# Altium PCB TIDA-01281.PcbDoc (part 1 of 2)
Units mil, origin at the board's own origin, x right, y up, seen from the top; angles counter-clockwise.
Board outline 2559.06 x 2165.35 mil, 4 copper layers (Top Layer, GND, SIGNAL, Bottom Layer), stack 60.234 mil thick; 109 components, 85 nets, 348 pads, 231 vias.
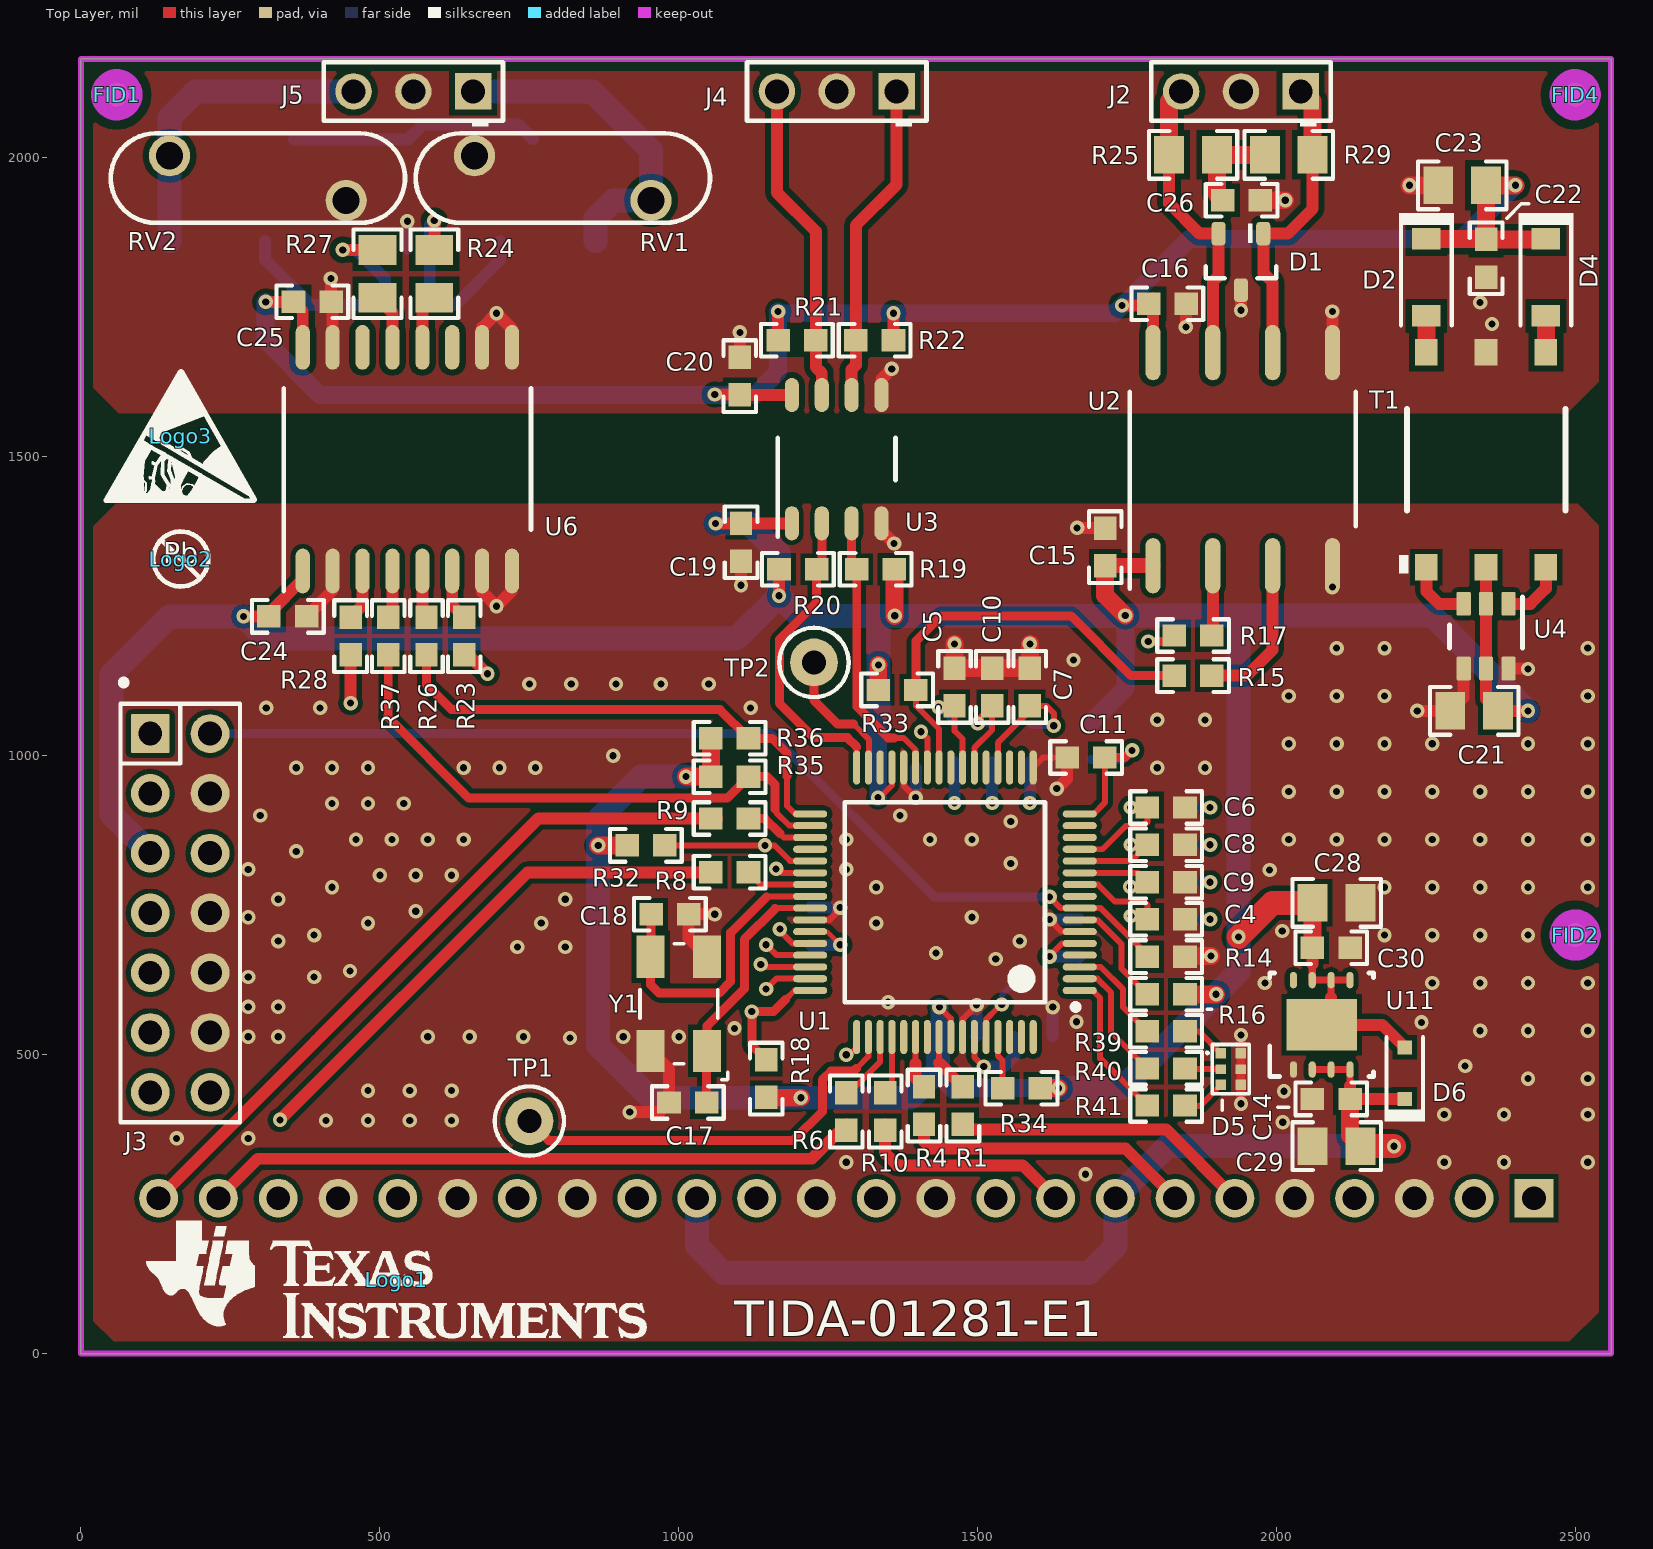
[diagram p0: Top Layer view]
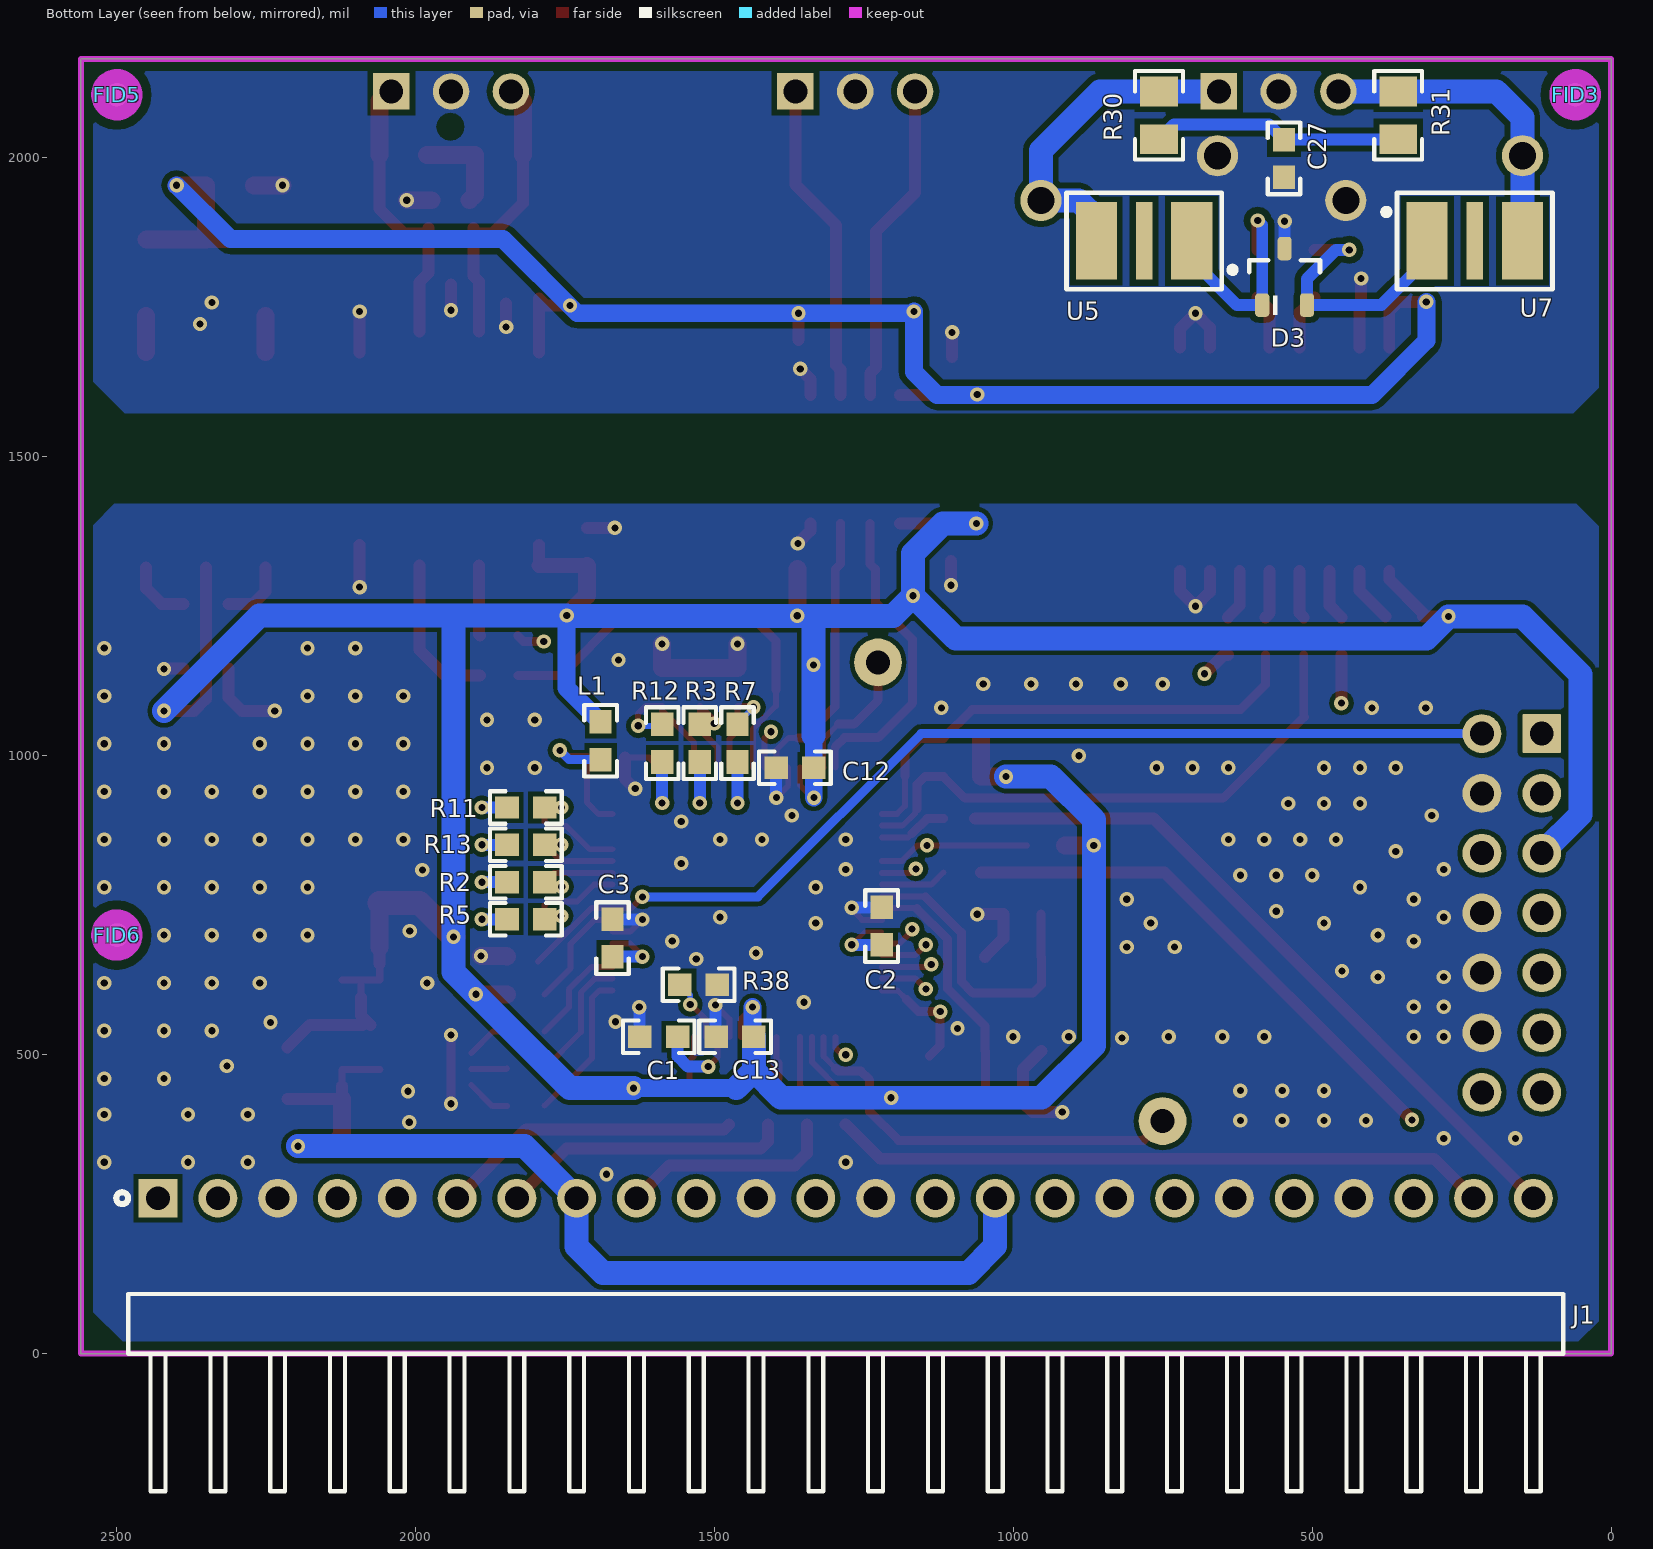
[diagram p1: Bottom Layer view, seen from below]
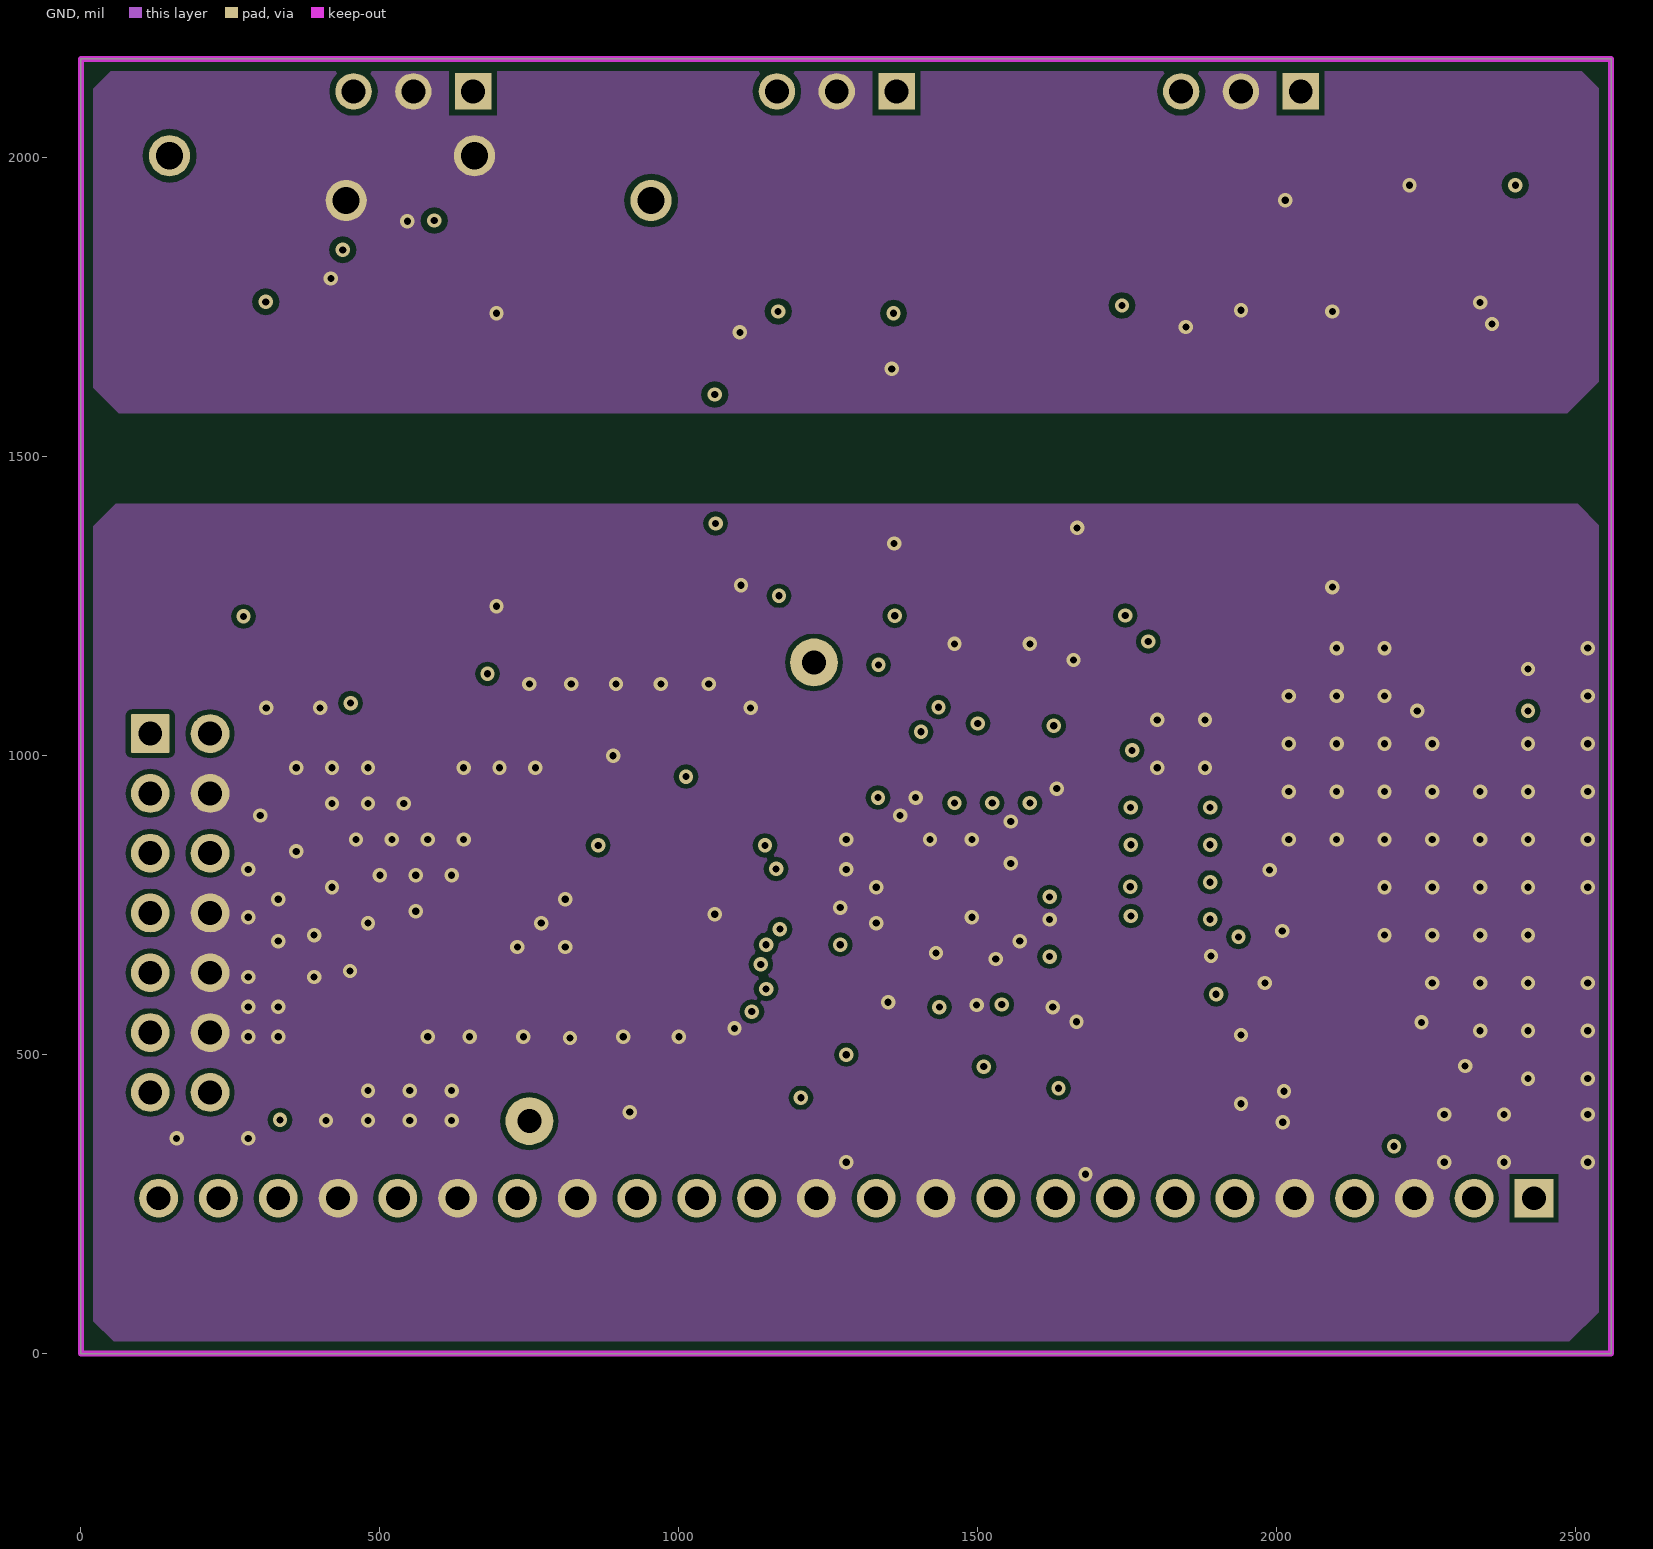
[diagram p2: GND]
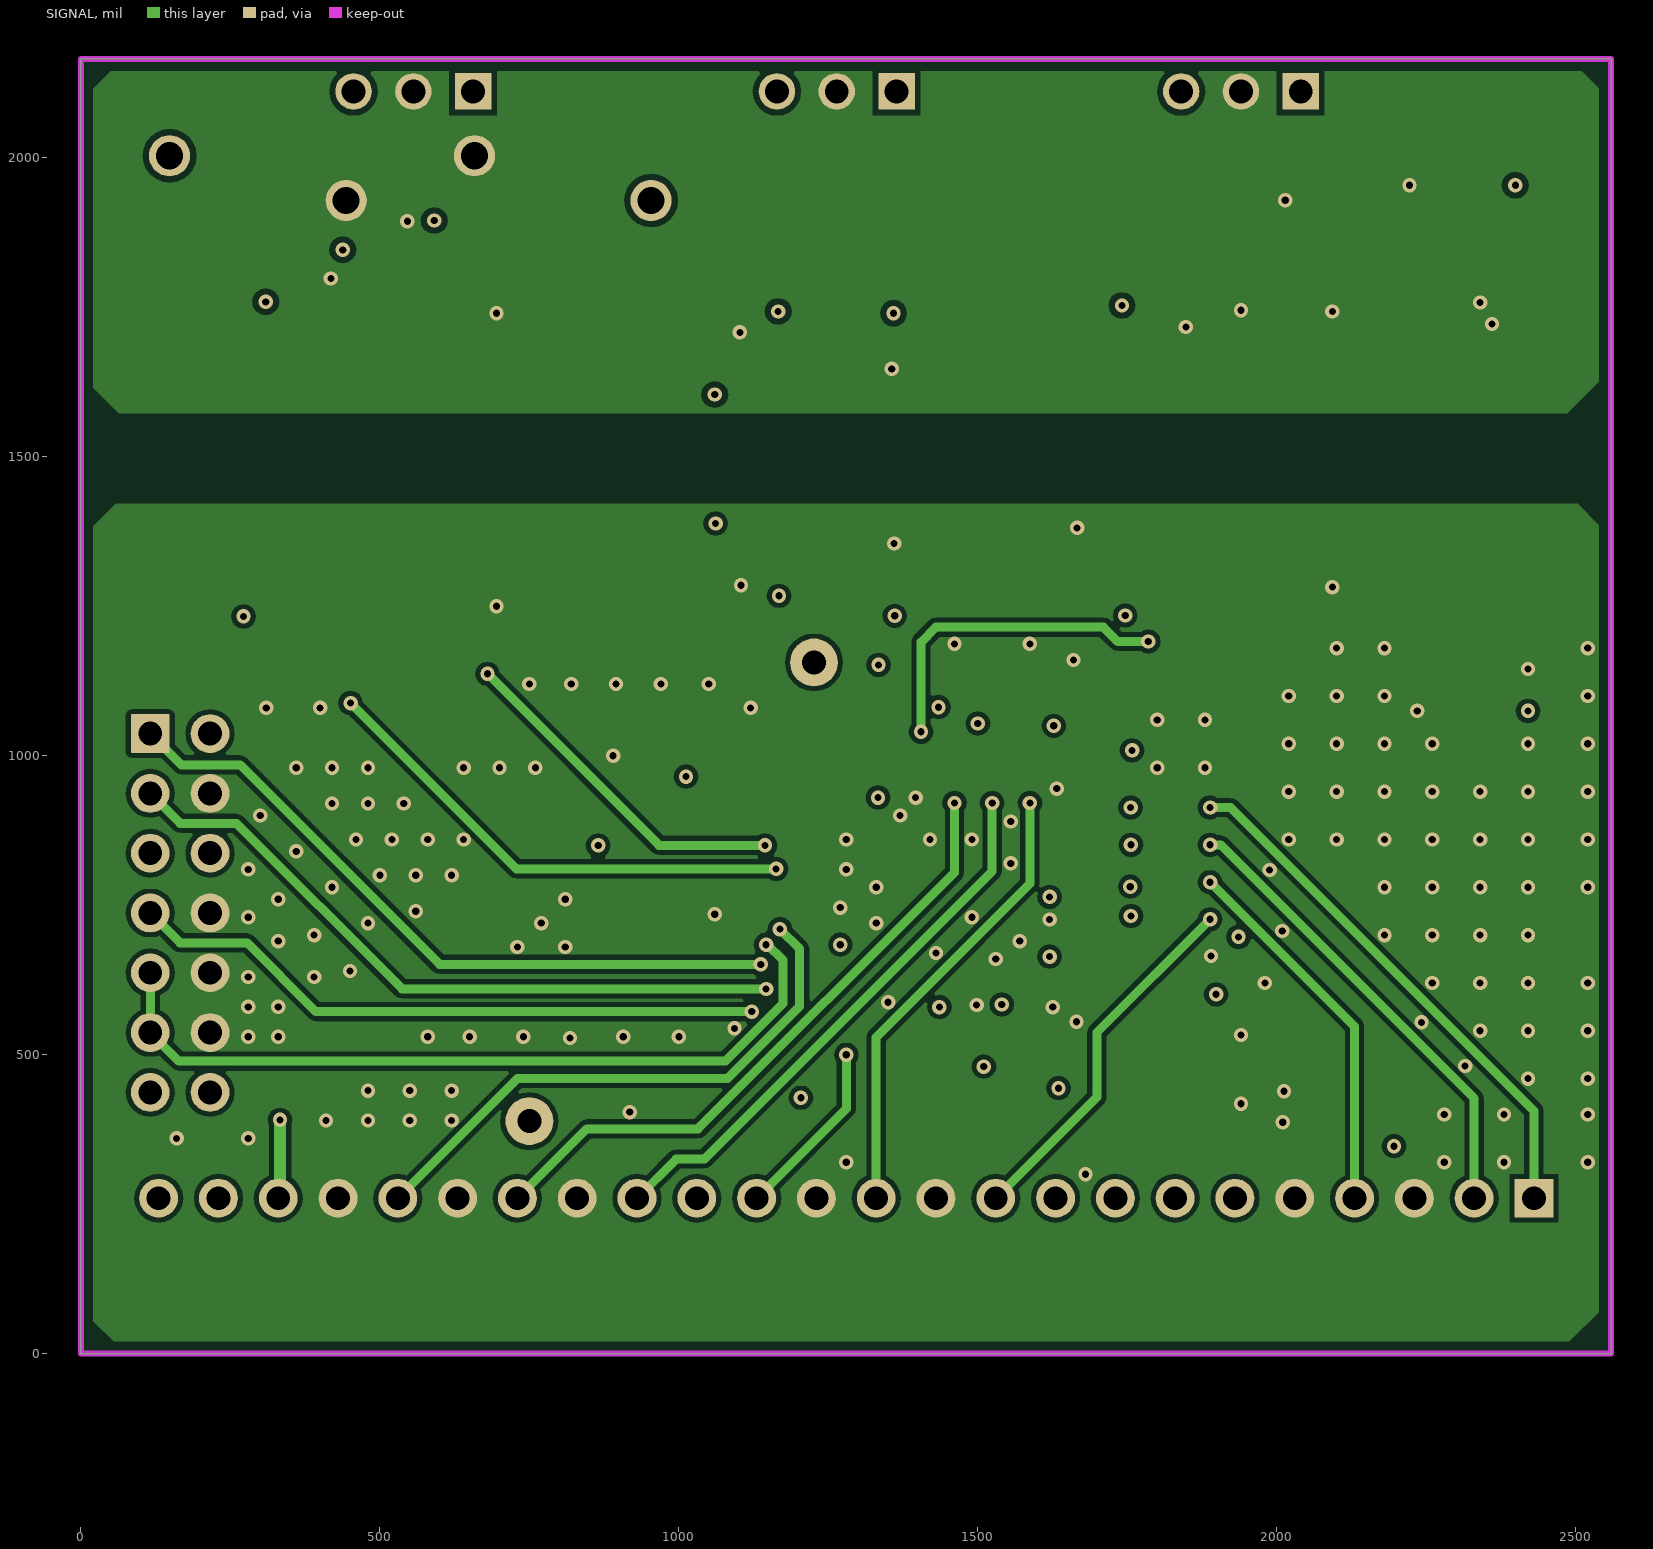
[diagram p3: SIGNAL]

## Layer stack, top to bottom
Top Solder: solder mask 0.4, Solder Resist, Dk 3.5
Top Layer: signal copper 0.7
Dielectric1: core 10, FR-4 High Tg, Dk 4.8
GND: signal copper 1.417
Dielectric 2: prepreg 36, FR-4 High Tg, Dk 4.2
SIGNAL: signal copper 1.417
Dielectric 3: core 10, FR-4 High Tg, Dk 4.2
Bottom Layer: signal copper 0.7
Bottom Solder: solder mask 0.4, Solder Resist, Dk 3.5

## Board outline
0,0 0,2165.36 2559.06,2165.36 2559.06,0

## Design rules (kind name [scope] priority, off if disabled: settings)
AcuteAngle [All] p1: minimum=4.50000000000000E+0001 checktracksonly=FALSE
AssemblyTestPointUsage [All] p1: valid=2
Clearance Clearance_Keepouts [((IsTrack Or IsArc) And Not InPoly) And IsFree and IsKeepOut vs ((IsTrack Or IsArc) And Not InPoly) And IsFree and IsKeepOut] p1: gap=20
Clearance Clearance_BoardEdge_MountingHoles [OnCopper and InComponentClass('Mounting Holes') vs IsKeepOut] p2: gap=40
Clearance Clearance_BoardEdge_Poly [OnCopper and InPoly vs IsKeepOut] p3: gap=15
Clearance Clearance_BoardEdge [OnCopper and Not InComponentClass('Logo') and not InComponentClass('FiducialMark') and not InRegion(1000,500,4000,800) and Not IsKeepout vs IsKeepOut] p4: gap=15
Clearance Clearance_Poly [InPolygon] p5: gap=8
Clearance [All] p6: gap=7.87
ComponentClearance ComponentClearance_MountingHoles_FiducialMarks [InComponentClass('Mounting Holes') vs InComponentClass('FiducialMark')] p1: gap=50 collisioncheckmode=3 verticalgap=10 showdistances=FALSE
ComponentClearance ComponentClearance_Shunt [InComponentClass('Header') vs InComponentClass('Shunt')] p2: gap=0 collisioncheckmode=3 verticalgap=0 showdistances=FALSE
ComponentClearance ComponentClearance_Logo [InComponentClass('Logo')] p3: gap=50 collisioncheckmode=3 verticalgap=10 showdistances=FALSE
ComponentClearance ComponentClearance_ScrewToNut [(HasFootprint('NY PMS 440 0025 PH')) vs (HasFootprint('Keystone_1902C'))] p4: gap=5 collisioncheckmode=3 verticalgap=10 showdistances=FALSE
ComponentClearance ComponentClearance_MountingHoles [InComponentClass('Mounting Holes')] p5: gap=200 collisioncheckmode=3 verticalgap=100000 showdistances=FALSE
ComponentClearance ComponentClearance_SmallPassives [HasFootprint('0201*') or HasFootprint('0402*') or HasFootprint('0508') or HasFootprint('0603*') or HasFootprint('0612') or HasFootprint('0805*') or HasFootprint('0815*') or HasFootprint('0830*') or HasFootprint('1206*') or HasFootprint('1210*') or HasFootprint('1808*') or HasFootprint('1812*') or HasFootprint('1825*') or HasFootprint('2010*') or HasFootprint('2220*') or HasFootprint('2225*') or HasFootprint('2512*') or HasFootprint('2728*') or HasFootprint('3518*') vs HasFootprint('0201*') or HasFootprint('0402*') or HasFootprint('0508') or HasFootprint('0603*') or HasFootprint('0612') or HasFootprint('0805*') or HasFootprint('0815*') or HasFootprint('0830*') or HasFootprint('1206*') or HasFootprint('1210*') or HasFootprint('1808*') or HasFootprint('1812*') or HasFootprint('1825*') or HasFootprint('2010*') or HasFootprint('2220*') or HasFootprint('2225*') or HasFootprint('2512*') or HasFootprint('2728*') or HasFootprint('3518*')] p6: gap=20 collisioncheckmode=3 verticalgap=10 showdistances=FALSE
ComponentClearance ComponentClearance_THtoSMT [IsThruComponent vs IsSMTComponent] p7: gap=20 collisioncheckmode=3 verticalgap=20 showdistances=FALSE
ComponentClearance ComponentClearance_THtoTH [IsThruComponent vs IsThruComponent] p8: gap=10 collisioncheckmode=3 verticalgap=10 showdistances=FALSE
ComponentClearance [All] p9: gap=20 collisioncheckmode=3 verticalgap=10 showdistances=FALSE
DiffPairsRouting [All] p1: maxlimit=100 minlimit=10 mostfreqgap=10 toplayer_minwidth=15 toplayer_maxwidth=15 toplayer_prefwidth=15 midlayer1_minwidth=15 midlayer1_maxwidth=15 midlayer1_prefwidth=15 midlayer2_minwidth=15 midlayer2_maxwidth=15 midlayer2_prefwidth=15 bottomlayer_minwidth=15 bottomlayer_maxwidth=15 bottomlayer_prefwidth=15 maxuncoupledlength=1000
FabricationTestPointUsage TestPointUsage [All] p1: valid=2 allowmultiple=FALSE
FabricationTestpoint Testpoint [All] p1: side=3 testpointundercomponent=TRUE minsize=40 maxsize=100 preferedsize=60 minholesize=0 maxholesize=40 preferedholesize=32 testpointgrid=1 allowsidetop=TRUE allowsidebottom=TRUE usegrid=TRUE gridtolerance=0.01
FanoutControl Fanout_LCC [IsLCC] p1: bgadir=Out bgaviamode=Centered fanoutstyle=Auto fanoutdirection=Alternating viagrid=1 // Fanout_LCC (Default Rule)
FanoutControl Fanout_BGA [IsBGA] p2: bgadir=Out bgaviamode=Centered fanoutstyle=Auto fanoutdirection=Alternating viagrid=1 // Fanout_BGA (Default Rule)
FanoutControl Fanout_Default [All] p4: bgadir=Out bgaviamode=Centered fanoutstyle=Auto fanoutdirection=Alternating viagrid=1 // Fanout_Default (Default Rule)
FanoutControl Fanout_Small [(CompPinCount < 5)] p5: bgadir=Out bgaviamode=Centered fanoutstyle=Auto fanoutdirection=OutThenIn viagrid=1 // Fanout_Small (Default Rule)
HoleSize [All] p1: absolutevalues=TRUE maxlimit=251 minlimit=8 maxpercent=80.000 minpercent=20.000
MinimumAnnularRing MinimumAnnularRing_ThermalPadVias [IsVia and InAnyComponent] p1: minimumring=5.91
MinimumAnnularRing [All] p2: minimumring=6
MinimumSolderMaskSliver MinimumSolderMaskSliver_Logo [InComponentClass('Logo') vs InComponentClass('Logo')] p1: minsoldermaskwidth=0.7
MinimumSolderMaskSliver [All] p2: minsoldermaskwidth=3.94
PlaneConnect [All] p1: planeconnectstyle=Relief reliefexpansion=10 reliefentries=4 reliefconductorwidth=10 reliefairgap=10
PolygonConnect [All] p1: connectstyle=Direct reliefconductorwidth=10 reliefentries=4 polygonreliefangle="90 Angle" airgapwidth=10
RoutingVias ThermalPadVias [IsVia and InAnyComponent] p1: holewidth=7.87 width=19.68 viastyle="Through Hole" minholewidth=7.87 minwidth=19.68 maxholewidth=12.99 maxwidth=23.62
RoutingVias [All] p2: holewidth=12 width=24 viastyle="Through Hole" minholewidth=12 minwidth=24 maxholewidth=40 maxwidth=65
SilkToBoardRegionClearance [Not ((IsComment or IsDesignator) And (Hide <> 'False')) and not InRegion(1000,500,4000,800)] p1:
SilkToSilkClearance SilkToSilkClearance_Pb-FreeLogo [(HasFootprint('Pb-Free_Overlay_Medium') OR HasFootprint('Pb-Free_Overlay_Small')) vs (HasFootprint('Pb-Free_Overlay_Medium') OR HasFootprint('Pb-Free_Overlay_Small'))] p1: silktosilkclearance=0
SilkToSilkClearance [All] p2: silktosilkclearance=4
SilkToSolderMaskClearance "Silk to Solder Mask Opening" [All] p1: minsilkscreentomaskgap=4 clearancetoexposedcopper=FALSE
SolderMaskExpansion [All] p1: expansion=1.97
UnpouredPolygon [All] p1: allowunpoured=FALSE
Width [All] p1: maxlimit=40 minlimit=8 preferedwidth=20 checkconnectedcopper=TRUE
14 further rules are at their usual default settings.

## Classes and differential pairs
component class TIDA-01281_Sheet1: C1 C2 C3 C4 C5 C6 C7 C8 C9 C10 C11 C12 C13 C14 C15 C16 C17 C18 C19 C20 C21 C22 C23 C24 C25 C26 C27 C28 C29 C30 D1 D2 D3 D4 D5 D6 J1 J2 J3 J4 J5 L1 R1 R2 R3 R4 R5 R6 R7 R8 R9 R10 R11 R12 R13 R14 R15 R16 R17 R18 R19 R20 R21 R22 R23 R24 R25 R26 R27 R28 R29 R30 R31 R32 R33 R34 R35 R36 R37 R38 R39 R40 R41 RV1 RV2 T1 TP1 TP2 U1 U2 U3 U4 U5 U6 U7 U11 Y1
component class AssemblyNote: ZZ1 ZZ2 ZZ3
component class FiducialMark: FID1 FID2 FID3 FID4 FID5 FID6
component class TIDA-01281_Hardware: FID1 FID2 FID3 FID4 FID5 FID6 Logo1 Logo2 Logo3 ZZ1 ZZ2 ZZ3
component class Logo: Logo1
component class Header: J1 J3

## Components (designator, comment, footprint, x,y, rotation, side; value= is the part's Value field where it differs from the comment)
C1 "C0603C125K9PACTU" 0603 1592.64,530 r0 bottom
C2 "C0603C125K9PACTU" 0603 1220,715 r90 bottom
C3 "C0603C125K9PACTU" 0603 1670,695 r270 bottom
C4 "06031C103JAT2A" 0603 1815,726.46 r0 top
C5 "06031C103JAT2A" 0603 1461,1115 r90 top
C6 "06031C103JAT2A" 0603 1815,913.46 r0 top
C7 "06031C103JAT2A" 0603 1587,1115 r90 top
C8 "UMK107AB7105KA-T" 0603 1815,851 r0 top
C9 "06031C102KAT2A" 0603 1815,788.46 r0 top
C10 "06031C102KAT2A" 0603 1524,1115 r90 top
C11 "C0603C125K9PACTU" 0603 1681,997 r180 top
C12 "C0603C125K9PACTU" 0603 1365,980 r0 bottom
C13 "C0603C125K9PACTU" 0603 1465,530 r0 bottom
C14 "06035A101JAT2A" 0603 2091,426 r0 top
C15 "06033C104JAT2A" 0603 1713,1349 r90 top
C16 "06033C104JAT2A" 0603 1817,1756 r0 top
C17 "GRM1885C2A150JA01D" 0603 1015,420 r180 top
C18 "GRM1885C2A150JA01D" 0603 985,735 r0 top
C19 "06033C104JAT2A" 0603 1104,1357 r270 top
C20 "06033C104JAT2A" 0603 1102,1635 r90 top
C21 "GRM21BZ71E106KE15L" 0805_HV 2330,1075 r0 top
C22 "8.850122061e+011" 0603 2350,1832 r90 top
C23 "GRM21BZ71E106KE15L" 0805_HV 2310,1954 r0 top
C24 "06033C104JAT2A" 0603 346,1233 r0 top
C25 "06033C104JAT2A" 0603 387,1759 r0 top
C26 "06031C472JAT2A" 0603 1941,1929 r180 top
C27 "06031C472JAT2A" 0603 547,1999 r90 bottom
C28 "06035A101JAT2A" 0603 2091,679 r180 top
C29 "GRM21BR61E106MA73" 0805_HV 2100,347 r0 top
C30 "GRM21BR61E106MA73" 0805_HV 2100,754 r180 top
D1 "CDSOT23-SM712" SOT-23 1940,1826 r270 top
D2 "1N5819HW-7-F" SOD-123 2250,1800 r270 top
D3 "CDSOT23-SM712" SOT-23 546,1801 r90 bottom
D4 "1N5819HW-7-F" SOD-123 2450,1800 r270 top
D5 "SMLP36RGB2W3" PicoLED_RGB_150x100 1923,476 r0 top
D6 "CMDSH2-3 TR" SOD-323 2214,469 r90 top
FID1 "Fiducial" Fiducial10-20#1 60,2105.36 r90 top
FID2 "Fiducial" Fiducial10-20#1 2499.06,700 r90 top
FID3 "Fiducial" Fiducial10-20#2 65,2100.36 r90 bottom
FID4 "Fiducial" Fiducial10-20#1 2499.06,2105.36 r90 top
FID5 "Fiducial" Fiducial10-20#1 2499.06,2105.36 r90 bottom
FID6 "Fiducial" Fiducial10-20#1 2499.06,700 r90 bottom
J1 "TSW-128-09-G-S-RE" CONN_TSW-128-09-X-S-RE 1080,260 r180 bottom
J2 "HTSW-103-09-G-S" Samtec_HTSW-103-09-x-S 1940,2111 r180 top
J3 "TSW-107-07-G-D" TSW-107-07-G-D 166,737 r270 top
J4 "HTSW-103-09-G-S" Samtec_HTSW-103-09-x-S 1264,2111 r180 top
J5 "HTSW-103-09-G-S" Samtec_HTSW-103-09-x-S 556,2111 r180 top
L1 "BLM18SG121TN1D" 0603 1690,1025 r270 bottom
Logo1 "Texas Instruments" TI_Stacked_Overlay_Small 528,124 r0 top
Logo2 "Pb-Free Symbol" Pb-Free_Overlay_Small 167,1329 r0 top
Logo3 "ESD Susceptible" ESD_Overlay_Medium 167,1534 r0 top
R1 "RC0603JR-070RL" 0603 1475,415 r270 top
R2 "CRCW06031K00JNEA" 0603 1815,788.46 r180 bottom
R3 "CRCW06031K00JNEA" 0603 1524,1021 r90 bottom
R4 "RC0603JR-070RL" 0603 1410,415 r270 top
R5 "CRCW06031K00JNEA" 0603 1815,726.46 r180 bottom
R6 "RC0603JR-070RL" 0603 1280,405 r270 top
R7 "CRCW06031K00JNEA" 0603 1461,1021 r90 bottom
R8 "RC0603JR-070RL" 0603 1085,805 r180 top
R9 "RC0603JR-070RL" 0603 1085,895 r180 top
R10 "RC0603JR-070RL" 0603 1345,405 r270 top
R11 "CRCW06031K00JNEA" 0603 1815,913.46 r180 bottom
R12 "CRCW06031K00JNEA" 0603 1587,1021 r90 bottom
R13 "CRCW06031K00JNEA" 0603 1815,851 r180 bottom
R14 "RC0603FR-074K7L" 0603 1815,664 r0 top
R15 "CRCW0603100RFKEA" 0603 1860,1134 r0 top
R16 "RC0603FR-074K7L" 0603 1815,601 r0 top
R17 "CRCW0603100RFKEA" 0603 1860,1201 r0 top
R18 "RC0603FR-0710KL" 0603 1146,460 r270 top
R19 "RC0603FR-074K7L" 0603 1329,1312 r180 top
R20 "RC0603FR-074K7L" 0603 1199,1312 r0 top
R21 "RC0603FR-074K7L" 0603 1197.5,1695 r0 top
R22 "RC0603FR-074K7L" 0603 1327.5,1695 r180 top
R23 "CRCW0603100RFKEA" 0603 641,1200 r270 top
R24 "CRT0805-BY-10R0ELF" 0805_HV 591,1806 r90 top
R25 "CRCW080560R4FKEA" 0805_HV 1860,2005 r0 top
R26 "CRCW0603100RFKEA" 0603 578,1200 r270 top
R27 "CRT0805-BY-10R0ELF" 0805_HV 496,1806 r90 top
R28 "CRCW0603100RFKEA" 0603 451,1200 r270 top
R29 "CRCW080560R4FKEA" 0805_HV 2020,2005 r0 top
R30 "CRCW080560R4FKEA" 0805_HV 756,2071 r270 bottom
R31 "CRCW080560R4FKEA" 0805_HV 356,2071 r90 bottom
R32 "CRCW06034K70JNEA" 0603 945,850 r0 top
R33 "CRCW06034K70JNEA" 0603 1365,1110 r0 top
R34 "RC0603FR-0710KL" 0603 1573,444 r0 top
R35 "CRCW06034K70JNEA" 0603 1085,965 r0 top
R36 "CRCW06034K70JNEA" 0603 1085,1029 r0 top
R37 "CRCW0603100RFKEA" 0603 514,1200 r270 top
R38 "RC0603FR-0710KL" 0603 1526,617 r180 bottom
R39 "CRCW06031K00JNEA" 0603 1815,539 r0 top
R40 "CRCW06031K00JNEA" 0603 1815,477 r0 top
R41 "CRCW06031K00JNEA" 0603 1815,415 r0 top
RV1 "MOV-10D201K" Bourns_MOV-10DxxxK 806,1966 r0 top
RV2 "MOV-10D201K" Bourns_MOV-10DxxxK 296,1966 r0 top
T1 "760390013" Wurth_760390013 2350,1495 r90 top
TP1 "5117" Keystone5117 750,389 r0 top
TP2 "5117" Keystone5117 1226,1156 r0 top
U1 "TMS320F28035PAGTR" PAG0064A_N 1445,755 r180 top
U2 "ISO1050DUB" DUB0008A_N 1943,1496 r90 top
U3 "ISO1541DR" D0008A_N 1264,1496 r90 top
U4 "SN6505BDBVR" DBV0006A_N 2350,1200 r270 top
U5 "TBU-CA065-200-WH" TBU-CA 781,1861 r0 bottom
U6 "ISO3082DW" DW0016A_N 546,1496 r90 top
U7 "TBU-CA065-200-WH" TBU-CA 228,1861 r180 bottom
U11 "TLV1117-50CDRJR" DRJ0008A 2075,550 r90 top
Y1 "ABM3B-20.000MHZ-10-1-U-T" ABRACON_ABM3B 1000,585 r180 top
ZZ1 "These assemblies are ESD sensitive, ESD precautions shall be observed." AssemblyNote -126,2792.6 r0 top
ZZ2 "These assemblies must be clean and free from flux and all contaminants. Use of no clean flux is not acceptable." AssemblyNote -126,2704.05 r0 top
ZZ3 "These assemblies must comply with workmanship standards IPC-A-610 Class 2, unless otherwise specified." AssemblyNote -126,2615.49 r0 top

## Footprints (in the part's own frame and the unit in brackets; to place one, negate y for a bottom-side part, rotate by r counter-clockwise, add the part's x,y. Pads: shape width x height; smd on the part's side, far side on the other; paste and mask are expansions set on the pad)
0603 [mm] "0603 from SM-752 data"
  rect 1x0.95 smd: 1(-0.8,0) 2(0.8,0)
  silkscreen extent -1.52,-0.69 1.52,0.69, body extent -0.87,-0.47 0.87,0.47, height 1
0805_HV [mil] "0805 with 30mil clearance between pads"
  rect 50x63 smd: 1(-40,0) 2(40,0)
  silkscreen extent -74,-40 74,40, body extent -43,-29 43,29, height 57
ABRACON_ABM3B [mm] "ABRACON"
  rect 1.2x1.8 smd: 1(-1.2,2) 2(-1.2,-2) 3(1.2,-2) 4(1.2,2)
  silkscreen extent -2.08,-2.55 1.65,3.22, body extent -1.65,-2.55 1.65,2.55, height 1.12
AssemblyNote [mil] "Assembly Note"
Bourns_MOV-10DxxxK [mm] "Bourns"
  round 1.75 hole 1.15: 1(-3.75,0.95) 2(3.75,-0.95)
  silkscreen extent -6.25,-1.9 6.25,1.9, body extent -6.23,-1.9 6.23,1.9, height 15.49
CONN_TSW-128-09-X-S-RE [mm] "Samtec 100mil, 1x28, Extended Right-angle"
  rect 1.65x1.65 hole 1.016 mask+0.064: 1(-34.29,0)
  round 1.65 hole 1.016 mask+0.064: 2(-31.75,0) 3(-29.21,0) 4(-26.67,0) 5(-24.13,0) 6(-21.59,0) 7(-19.05,0) 8(-16.51,0) 9(-13.97,0) 10(-11.43,0) 11(-8.89,0) 12(-6.35,0) 13(-3.81,0) 14(-1.27,0) 15(1.27,0) 16(3.81,0) 17(6.35,0) 18(8.89,0) 19(11.43,0) 20(13.97,0) 21(16.51,0) 22(19.05,0) 23(21.59,0) 24(24.13,0)
  silkscreen extent -35.56,-12.45 25.4,-4.06
D0008A_N [mm] "SOIC, 8-Leads, Body 4.9x3.9mm, Pitch 1.27mm, IPC Medium Density"
  oval 1.45x0.6 smd: 1(-2.725,1.905) 2(-2.725,0.635) 3(-2.725,-0.635) 4(-2.725,-1.905) 5(2.725,-1.905) 6(2.725,-0.635) 7(2.725,0.635) 8(2.725,1.905)
  silkscreen extent -3.3,-2.5 0.9,2.5, body extent -3,-2.45 3,2.45, height 1.63
DBV0006A_N [mm] "SOT23, 6-Leads, Body 2.9x1.6mm, Pitch 0.95mm, Lead Span 2.8mm, IPC Medium Density"
  rrect17% 1x0.6 smd: 1(-1.375,0.95) 2(-1.375,0) 3(-1.375,-0.95) 4(1.375,-0.95) 5(1.375,0) 6(1.375,0.95)
  silkscreen extent -1.68,-1.55 0.5,1.55, body extent -1.42,-1.46 1.42,1.46, height 1.12
DRJ0008A [mm] "SON, 8-Leads, Body 4x4mm, Pitch 0.8mm, Thermal Pad 3x2.2mm, TI Recommended"
  oval 0.7x0.3 smd: 1(-1.9,1.2) 2(-1.9,0.4) 3(-1.9,-0.4) 4(-1.9,-1.2) 5(1.9,-1.2) 6(1.9,-0.4) 7(1.9,0.4) 8(1.9,1.2)
  rect 2.2x3 smd paste-1.1: 9(0,0)
  silkscreen extent -2.2,-2.2 2.2,2.2, body extent -2.05,-2.05 2.05,2.05, height 0.81
DUB0008A_N [mm] "SOP, 8-Leads, Body 9.5x6.62mm, Pitch 2.54mm, IPC Medium Density"
  oval 2.35x0.65 smd: 1(-4.525,3.81) 2(-4.525,1.27) 3(-4.525,-1.27) 4(-4.525,-3.81) 5(4.525,-3.81) 6(4.525,-1.27) 7(4.525,1.27) 8(4.525,3.81)
  silkscreen extent -5.5,-4.8 2.85,4.8, body extent -5.21,-4.75 5.21,4.75, height 4.85
DW0016A_N [mm] "SOIC, 16-Leads, Body 10.3x7.5mm, Pitch 1.27mm, IPC Medium Density"
  oval 1.9x0.6 smd: 1(-4.75,4.445) 2(-4.75,3.175) 3(-4.75,1.905) 4(-4.75,0.635) 5(-4.75,-0.635) 6(-4.75,-1.905) 7(-4.75,-3.175) 8(-4.75,-4.445) 9(4.75,-4.445) 10(4.75,-3.175) 11(4.75,-1.905) 12(4.75,-0.635) 13(4.75,0.635) 14(4.75,1.905) 15(4.75,3.175) 16(4.75,4.445)
  silkscreen extent -5.6,-5.25 3,5.25, body extent -5.14,-5.13 5.14,5.13, height 2.54
ESD_Overlay_Medium [mil]
  silkscreen extent -127,-109 125,110
Fiducial10-20#1 [mm]
  round 1 smd mask+0.5: 1(0,0)
  Top Layer keep-out circle w1.178: c0,0 r0.5
Fiducial10-20#2 [mm]
  round 1 smd mask+0.5: 1(0.127,-0.127)
  Top Layer keep-out circle w1.178: c0.127,-0.127 r0.5
Keystone5117 [mil] "For Keystone 500x miniature loop terminals"
  round 80 hole 40: 1(0,0)
  silkscreen extent -58,-58 58,58, body extent -49,-49 49,49, height 182
PAG0064A_N [mm] "Thin QFP, 64-Leads, Body 10x10mm, Pitch 0.5mm, IPC Medium Density"
  oval 1.45x0.3 smd: 1(-5.725,3.75) 2(-5.725,3.25) 3(-5.725,2.75) 4(-5.725,2.25) 5(-5.725,1.75) 6(-5.725,1.25) 7(-5.725,0.75) 8(-5.725,0.25) 9(-5.725,-0.25) 10(-5.725,-0.75) 11(-5.725,-1.25) 12(-5.725,-1.75) 13(-5.725,-2.25) 14(-5.725,-2.75) 15(-5.725,-3.25) 16(-5.725,-3.75) 33(5.725,-3.75) 34(5.725,-3.25) 35(5.725,-2.75) 36(5.725,-2.25) 37(5.725,-1.75) 38(5.725,-1.25) 39(5.725,-0.75) 40(5.725,-0.25) 41(5.725,0.25) 42(5.725,0.75) 43(5.725,1.25) 44(5.725,1.75) 45(5.725,2.25) 46(5.725,2.75) 47(5.725,3.25) 48(5.725,3.75)
  oval 0.3x1.45 smd: 17(-3.75,-5.725) 18(-3.25,-5.725) 19(-2.75,-5.725) 20(-2.25,-5.725) 21(-1.75,-5.725) 22(-1.25,-5.725) 23(-0.75,-5.725) 24(-0.25,-5.725) 25(0.25,-5.725) 26(0.75,-5.725) 27(1.25,-5.725) 28(1.75,-5.725) 29(2.25,-5.725) 30(2.75,-5.725) 31(3.25,-5.725) 32(3.75,-5.725) 49(3.75,5.725) 50(3.25,5.725) 51(2.75,5.725) 52(2.25,5.725) 53(1.75,5.725) 54(1.25,5.725) 55(0.75,5.725) 56(0.25,5.725) 57(-0.25,5.725) 58(-0.75,5.725) 59(-1.25,5.725) 60(-1.75,5.725) 61(-2.25,5.725) 62(-2.75,5.725) 63(-3.25,5.725) 64(-3.75,5.725)
  silkscreen extent -5.68,-4.25 4.25,4.57, body extent -6,-6 6,6, height 1.09
Pb-Free_Overlay_Small [mil]
  silkscreen extent -46,-46 46,46
PicoLED_RGB_150x100 [mm] "SMD, 6-Leads, Body 1.5x1mm"
  rect 0.45x0.45 smd: 1(-0.425,0.675) 3(-0.425,-0.675) 4(0.425,-0.675) 6(0.425,0.675)
  rect 0.45x0.4 smd: 2(-0.425,0) 5(0.425,0)
  silkscreen extent -1.04,0.64 -0.94,0.74, body extent -0.5,-0.75 0.5,0.75, height 0.25
Samtec_HTSW-103-09-x-S [mm] "Header, 3x1, 2.54mm, TH"
  rect 1.55x1.55 hole 1.016: 1(-2.54,0)
  round 1.55 hole 1.016: 2(0,0) 3(2.54,0)
  silkscreen extent -3.81,-1.24 3.81,1.5, body extent -3.81,-1.24 3.81,1.24, height 8.38
SOD-123 [mm] "On Semi recommended land pattern"
  rect 0.915x1.22 smd: 1(-1.637,0) 2(1.637,0)
  silkscreen extent -2.74,-1.17 2.03,1.17, body extent -1.93,-0.9 1.93,0.9, height 1.35
SOD-323 [mm] "NXP recommended land pattern"
  rect 0.6x0.6 smd paste-0.05: 1(-1.1,0) 2(1.1,0)
  silkscreen extent -2.06,-0.86 1.53,0.86, body extent -1.3,-0.67 1.3,0.68, height 1.1
SOT-23 [mm] "SOT23, 3-Leads, Body 2.9x1.3mm, Pitch 0.95mm, Lead Span 2.5mm, IPC Medium Density"
  rrect50% 1x0.6 smd: 1(-1.2,0.95) 2(-1.2,-0.95) 3(1.2,0)
  silkscreen extent -1.63,-1.5 0.7,1.5, body extent -1.16,-1.45 1.21,1.45, height 1
TBU-CA [mm] "Bourns"
  rect 1.75x3.3 smd paste-0.012 mask+0.05: 1(-2.025,0) 3(2.025,0)
  rect 0.7x3.3 smd paste-0.012 mask+0.05: 2(0,0)
  silkscreen extent -3.89,-2.05 3.3,2.05, body extent -3.25,-2 3.25,2, height 0.87
TI_Stacked_Overlay_Small [mil]
  silkscreen extent -418,-98 418,98
TSW-107-07-G-D [mm] "Samtec 100mil, 2x7, 230 mil above insulator"
  rrect6% 1.65x1.65 hole 1.016: 1(-7.62,-1.27)
  round 1.65 hole 1.016: 2(-7.62,1.27) 3(-5.08,-1.27) 4(-5.08,1.27) 5(-2.54,-1.27) 6(-2.54,1.27) 7(0,-1.27) 8(0,1.27) 9(2.54,-1.27) 10(2.54,1.27) 11(5.08,-1.27) 12(5.08,1.27) 13(7.62,-1.27) 14(7.62,1.27)
  silkscreen extent -9.91,-2.54 8.89,2.54, body extent -8.89,-2.54 8.89,2.54, height 8.38
Wurth_760390013 [mil] "Wurth"
  rect 44x38 smd: 1(-180,100) 2(-180,0) 3(-180,-100) 4(180,-100) 5(180,0) 6(180,100)
  silkscreen extent -190,-132 85,145, body extent -198,-135 198,130, height 166

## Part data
C1 C2 C3 C11 C12 C13: "CAP, CERM, 1.2 µF, 6.3 V, +/- 10%, X5R, 0603"
C4 C5 C6 C7: "CAP, CERM, 0.01 µF, 100 V, +/- 5%, X7R, 0603"
C8: "CAP, CERM, 1 µF, 50 V, +/- 10%, X7R, 0603"
C9 C10: "CAP, CERM, 1000 pF, 100 V, +/- 10%, X7R, 0603"
C14 C28: "CAP, CERM, 100 pF, 50 V, +/- 5%, C0G/NP0, 0603"
C15 C16 C19 C20 C24 C25: "CAP, CERM, 0.1 µF, 25 V, +/- 5%, X7R, 0603"
C17 C18: "CAP, CERM, 15 pF, 100 V, +/- 5%, C0G/NP0, 0603"
C21 C23: "CAP, CERM, 10 µF, 25 V, +/- 10%, X7R, 0805"
C22: "CAP, CERM, 0.1 µF, 50 V, +/- 10%, X7R, 0603"
C26 C27: "CAP, CERM, 4700 pF, 100 V, +/- 5%, X7R, 0603"
C29 C30: "CAP, CERM, 10 µF, 25 V, +/- 20%, X5R, 0805"
D1 D3: "Diode, TVS, Bi, 7 V, 400 W, SOT-23"
D2 D4: "Diode, Schottky, 40 V, 1 A, SOD-123"
D5: "LED, Rgb, SMD"
D6: "Diode, Schottky, 30 V, 0.2 A, SOD-323"
FID1 FID2 FID3 FID4 FID5 FID6: "Fiducial mark.  There is nothing to buy or mount."
J1: "Header, 100mil, 28x1, Gold, R/A, TH"
J2 J4 J5: "Header, 100mil, 3x1, Gold, TH"
J3: "Header, 100mil, 7x2, Gold, TH"
L1: "Ferrite Bead, 120 ohm @ 100 MHz, 3 A, 0603"
Logo1: library part TI_Logo, "Texas Instrument Corporate Signature"
Logo2: library part Pb-Free
Logo3: library part ESD_Susceptible, "ESD Susceptible Symbol"
R1 R4 R6 R8 R9 R10: "RES, 0, 5%, 0.1 W, 0603"
R2 R3 R5 R7 R11 R12 R13 R39 R40 R41: "RES, 1.0 k, 5%, 0.1 W, 0603"
R14 R16 R19 R20 R21 R22: "RES, 4.70 k, 1%, 0.1 W, 0603"
R15 R17 R23 R26 R28 R37: "RES, 100, 1%, 0.1 W, 0603"
R18 R34 R38: "RES, 10.0 k, 1%, 0.1 W, 0603"
R24 R27: "RES, 10.0, 0.1%, 0.1 W, 0805"
R25 R29 R30 R31: "RES, 60.4, 1%, 0.125 W, 0805"
R32 R33 R35 R36: "RES, 4.7 k, 5%, 0.1 W, 0603"
RV1 RV2: "Metal Oxide Varistor, TH"
T1: "Transformer, 475 uH, SMT"
TP1 TP2: "Test Point, Miniature, Blue, TH"
U1: "Piccolo(TM) Microcontrollers, PAG0064A"
U2: "Isolated CAN Transceiver, -55 to 105 degC, 8-pin SOP (DUB), Green (RoHS & no Sb/Br)"
U3: "Low-Power Bidirectional I2C Isolators, D0008A"
U4: "LOW-NOISE 1A TRANSFORMER DRIVERS FOR ISOLATED POWER SUPPLIES, DBV0006A"
U5 U7: "TBU-CA series TBU High-Speed Protectors, TBU-CA"
U6: "Isolated RS-485 Transceiver, 0.2 Mbps, 5 V, Half Duplex, -40 to 85 degC, 16-pin SOIC (DW), Green (RoHS & no Sb/Br)"
U11: "LDO with 6.4 to 15 V Input and 5 V Output, 0 to 125 degC, 8-Pin SON (DRJ), Green (RoHS & no Sb/Br)"
Y1: "Crystal, 20 MHz, 10 pF, SMD"
ZZ1 ZZ2 ZZ3: library part AssemblyNote

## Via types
v1: diameter 24, hole 12, Top Layer to Bottom Layer, 231 vias

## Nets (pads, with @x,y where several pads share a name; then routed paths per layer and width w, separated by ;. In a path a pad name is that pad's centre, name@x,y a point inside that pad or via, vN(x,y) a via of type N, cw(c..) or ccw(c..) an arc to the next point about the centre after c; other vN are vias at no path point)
CAN_RX: R17.1 U1.26 | length 662.5
  Top Layer w10: v1(1405,1040) 1415.47,1029.53 U1.26@1415.47,980.39 U1.26@1415.87,980.8
  Top Layer w15: v1(1785,1191) 1818.5,1191 R17.1@1828.5,1201
  SIGNAL w15: v1(1405,1040) 1405,1190 1430,1215 1710,1215 1734,1191 v1(1785,1191)
CAN_TX: R15.1 R33.2 U1.25 | length 718.3
  Top Layer w10: R33.2@1396.5,1110 1396.5,1083.5 1415.13,1064.87 1415.3,1064.87 1435.16,1045.02 U1.25@1435.16,980.39
  Top Layer w15: R33.2@1396.5,1110 1396.5,1191.5 1439,1234 1656,1234 1756,1134 R15.1@1828.5,1134
CLAMP_PWM: J1.9 R10.2 | length 364.6
  Top Layer w20: R10.2@1345,383.51 1345,335 1365,315 1575,315 J1.9@1630,260
COMM_5V: C16.1 C20.1 C22.2 C23.2 C25.1 D2.1 D4.1 R21.1 R22.1 U2.8 U3.8 U6.16 | length 3236.6
  Top Layer w20: v1(309,1759) C25.1@355.5,1759 371,1743.5 U6.16@371,1683.01 ; v1(1060,1604) 1101.51,1604 C20.1@1102,1603.5 1102.22,1603.28 U3.8@1189,1603.28 ; R21.1@1166.01,1695 v1(1166.01,1742.99) ; R22.1@1359,1695 v1(1359,1740) ; v1(1741,1753) 1781.5,1753 1793,1764.5 U2.8@1793,1674.15
  Top Layer w30: D2.1@2250,1864.47 2349.03,1864.47 C22.2@2350,1863.5 ; v1(2399,1954) C23.2@2350,1954 C22.2@2350,1863.5 ; D4.1@2449.03,1863.5 C22.2@2350,1863.5
  Bottom Layer w30: v1(309,1759) 309,1694 399.5,1603.5 1063.5,1603.5 1127.5,1603.5 1166.01,1642.01 v1(1166.01,1742.99) 1169,1740 v1(1359,1740) 1728.99,1740 1852.99,1864 2309,1864 v1(2399,1954)
COMM_GND: C16.2 C20.2 C22.1 C23.1 C25.2 C26.1 C27.1 D1.3 D3.3 J2.2 J4.2 J5.2 RV1.1 RV2.2 T1.5 U2.5 U3.5 U6.9 U6.10 U6.15 | length 630.3
  Top Layer w20: v1(418,1798.01) 418.5,1798.51 C25.2@418.5,1759 421,1756.5 U6.15@421,1683.01 ; U6.10@671,1683.01 671,1716 v1(695,1740) 721,1714 U6.9@721,1683.01 ; C20.2@1102,1666.5 v1(1102,1708) ; U3.5@1339,1603.28 1339,1630 v1(1356,1647) ; v1(1848,1717) 1848.5,1717.5 C16.2@1848.5,1756 ; v1(1940,1745) D1.3@1940,1787.76 ; U2.5@2093,1674.15 v1(2093,1743)
  Top Layer w30: C26.1@1972.5,1929 v1(2014,1929) ; v1(2222,1954) C23.1@2270,1954
  Bottom Layer w20: D3.3@546,1848.25 v1(546,1894)
  other v1: 2360,1722 2340,1758
FLYBOOST_PWM: J1.22 R8.2 | length 1024.2
  Top Layer w20: v1(333,391) 747,805 R8.2@1053.5,805
  SIGNAL w20: J1.22@330,260 333,263 v1(333,391)
HV_PH1_PWM: J1.23 R6.2 | length 1101.2
  Top Layer w20: J1.23@230,260 296,326 1222.5,326 R6.2@1280,383.51
HV_PH2_PWM: J1.24 R9.2 | length 1196.6
  Top Layer w20: J1.24@130,260 393.43,523.43 393.58,523.43 404.06,533.9 404.06,534.06 765,895 R9.2@1063.5,895
I2C_SCL: R19.2 U1.27 U3.3 | length 467.6
  Top Layer w10: 1360,1030 1375.69,1030 1394.88,1010.81 1394.88,1010.31 1395.79,1009.41 U1.27@1395.79,980.39
  Top Layer w15: U3.3@1289,1388.72 1289,1320.51 R19.2@1297.5,1312 1297.5,1082.5 1350,1030 1360,1030
I2C_SDA: R20.2 U1.32 U3.2 | length 524.1
  Top Layer w10: U1.32@1297.36,980.39 1297.36,1014.64
  Top Layer w15: U3.2@1239,1388.72 1239,1320.51 R20.2@1230.5,1312 1230.5,1256.5 1168,1194 1168,1088 1225.87,1030.13 1281.87,1030.13 1297.36,1014.64
IBAT_ALERT: J1.14 U1.49 | length 342.4
  Top Layer w10: v1(1280,500) 1286,500 1297.36,511.36 U1.49@1297.36,529.61
  SIGNAL w15: J1.14@1130,260 1280,410 v1(1280,500)
IBAT_HS: J1.12 R12.1 | length 836
  SIGNAL w15: J1.12@1330,260 1330,529 1361.3,560.3 ; 1361.34,560.3 1587,785.97 v1(1587,921)
  Bottom Layer w20: v1(1587,921) R12.1@1587,989.5
IBAT_LS: J1.4 R2.1 | length 670.5
  SIGNAL w15: v1(1888.46,788.46) 2130,546.91 J1.4@2130,260
  Bottom Layer w20: R2.1@1846.5,788.46 v1(1888.46,788.46)
IBUS: J1.16 R3.1 | length 1003.1
  SIGNAL w15: J1.16@930,260 995.5,325.5 1042.5,325.5 1524,807 v1(1524,921)
  Bottom Layer w20: v1(1524,921) R3.1@1524,989.5
LED1: R39.1 U1.3 | length 175.1
  Top Layer w10: U1.3@1670.39,646.73 1705.5,646.73 1743,609.23 1743,579.5 R39.1@1783.5,539
LED2: R40.1 U1.2 | length 214.2
  Top Layer w10: U1.2@1670.39,627.05 1699.91,627.05 1722.63,604.33 1722.63,537.88 R40.1@1783.5,477
LED3: R41.1 U1.1 | length 251.9
  Top Layer w10: U1.1@1670.39,607.36 1692.08,607.36 1704.63,594.82 1704.63,493.88 R41.1@1783.5,415
LV_AUX_3V3: C14.2 C29.2 D6.1 J1.8 J1.15 U11.2 U11.3 U11.4 | length 1746.1
  Top Layer w12: U11.2@2059.25,475.2 U11.3@2090.75,475.2 U11.4@2122.24,475.2 2122.24,448
  Top Layer w20: 2122.24,448 2122.24,426.25 C14.2@2122.5,426 2213.69,426 D6.1@2214,425.69
  Top Layer w30: C14.2@2122.5,426 2122.5,364.5 C29.2@2140,347
  Top Layer w40: C29.2@2140,347 v1(2196,347)
  Bottom Layer w40: J1.15@1030,260 1030,180 1075,135 1686,135 1730,179 J1.8@1730,260 1817,347 v1(2196,347)
LV_PH1_PWM: J1.7 R4.2 | length 487.9
  Top Layer w20: R4.2@1410,383.51 1410,355 1422.12,342.88 1747.13,342.88 J1.7@1830,260
LV_PH2_PWM: J1.6 R1.2 | length 506.2
  Top Layer w20: R1.2@1475,383.51 1483.51,375 1815,375 J1.6@1930,260
NetC1_1: C1.1 U1.59 | length 147.2
  Top Layer w10: U1.59@1494.21,529.61 1494.21,495.79 v1(1510,480)
  Bottom Layer w20: v1(1510,480) 1544,480 1561.14,497.14 C1.1@1561.14,530
NetC2_1: C2.1 U1.43 | length 109.6
  Top Layer w8: U1.43@1219.61,705.79 1248.21,705.79 v1(1270,684)
  Bottom Layer w20: C2.1@1220,683.5 1269.5,683.5 v1(1270,684)
NetC3_2: C3.2 U1.5 | length 110.5
  Top Layer w10: v1(1620,664) 1620,665.22 1640.88,686.1 U1.5@1670.39,686.1
  Bottom Layer w20: v1(1620,664) 1669.5,664 C3.2@1670,663.51
NetC4_1: C4.1 R5.2 U1.10 | length 181
  Top Layer w10: U1.10@1670.39,784.53 1700.88,784.53 1729.28,756.13 1777.87,756.13 1783.5,750.5 C4.1@1783.5,726.46 1777.96,732 v1(1756,732)
NetC5_1: C5.1 R7.2 U1.23 | length 177.2
  Top Layer w10: U1.23@1474.53,980.39 1474.53,1027.97 1461,1041.5 C5.1@1461,1083.5 1436.49,1083.5 v1@1434.45,1081.46 ; v1@1434.45,1081.46 v1(1434.17,1081.18) 1433.9,1081.46 v1@1434.45,1081.46
  Bottom Layer w10: v1(1434.17,1081.18) 1461,1054.35 R7.2@1461,1052.5
NetC6_1: C6.1 R11.2 U1.13 | length 184
  Top Layer w10: U1.13@1670.39,843.58 1708.58,843.58 1747.57,882.57 1776.57,882.57 1783.5,889.5 C6.1@1783.5,913.46 v1(1755.54,913.46)
NetC7_1: C7.1 R12.2 U1.20 | length 232.4
  Top Layer w10: U1.20@1533.58,980.39 1533.58,1021.58 1587,1075 C7.1@1587,1083.5 1614.5,1083.5 1627,1071 v1(1627,1050)
  Bottom Layer w10: R12.2@1587,1052.5 1589.5,1050 v1(1627,1050)
NetC8_1: C8.1 R13.2 U1.12 | length 151.8
  Top Layer w10: U1.12@1670.39,823.9 1756.4,823.9 C8.1@1783.5,851 v1(1756.02,851)
NetC9_1: C9.1 R2.2 U1.11 | length 152.9
  Top Layer w10: U1.11@1670.39,804.21 1767.75,804.21 C9.1@1783.5,788.46 1775.05,780 1773.05,782 1772.05,781 v1(1755,781)
NetC10_1: C10.1 R3.2 U1.22 | length 181.6
  Top Layer w10: U1.22@1494.21,980.39 1494.21,1013.21 1524,1043 C10.1@1524,1083.5 1500,1059.5 v1(1500,1054)
  Bottom Layer w10: v1(1500,1054) 1517.5,1054 1521.5,1050 R3.2@1524,1052.5
NetC11_1: C11.1 L1.2 U1.16 | length 250.3
  Top Layer w10: U1.16@1670.39,902.64 1693.64,902.64 1712.5,921.5 C11.1@1712.5,997
  Top Layer w15: C11.1@1712.5,997 1746,997 v1(1758,1009)
  Bottom Layer w15: L1.2@1690,993.51 1742.5,993.51 v1(1758,1009)
NetC26_2: C26.2 R25.2 R29.1 | length 159.9
  Top Layer w30: C26.2@1909.5,1929 1900,1938.5 R25.2@1900,2005 R29.1@1980,2005
NetC27_2: C27.2 R30.2 R31.1 | length 420.9
  Bottom Layer w20: R31.1@356,2031 356.51,2030.5 C27.2@547,2030.5 572.23,2055.73 731.28,2055.73 R30.2@756,2031
NetD1_1: D1.1 J2.1 R29.2 U2.6 | length 487.7
  Top Layer w20: D1.1@1977.4,1882.25 D1.1@1977.4,1873.24 ; U2.6@1993,1709.15 1993,1791.84 1977.4,1807.44 D1.1@1977.4,1873.24 ; R29.2@2060,2005 2060,1915 2018.24,1873.24 D1.1@1977.4,1873.24
  Top Layer w30: J2.1@2040,2115 2060,2095 R29.2@2060,2005
NetD1_2: D1.2 J2.3 R25.1 U2.7 | length 480
  Top Layer w20: R25.1@1820,2005 1820,1924 1870.76,1873.24 D1.2@1902.6,1873.24 ; U2.7@1893,1709.15 1893,1793 1902.6,1802.6 D1.2@1902.6,1882.25
  Top Layer w30: R25.1@1820,2005 1820,2095 J2.3@1840,2115
NetD2_2: D2.2 T1.6 | length 60.6
  Top Layer w30: T1.6@2250,1674.92 D2.2@2250,1735.53
NetD3_1: D3.1 R24.2 U5.1 | length 374.3
  Top Layer w20: R24.2@591,1846 v1(591,1895)
  Bottom Layer w20: v1(591,1895) 583.4,1887.4 D3.1@583.4,1753.76 625.76,1753.76 701.28,1829.28 U5.1@701.28,1861
NetD3_2: D3.2 R27.2 U7.1 | length 455.7
  Top Layer w20: v1(438,1846) R27.2@496,1846
  Bottom Layer w20: U7.1@307.73,1861 307.73,1830.27 384.24,1753.76 D3.2@508.6,1753.76 508.6,1797.4 460,1846 v1(438,1846)
NetD4_2: D4.2 T1.4 | length 60.6
  Top Layer w30: T1.4@2450,1674.92 D4.2@2450,1735.53
NetD5_1: D5.1 R39.2 | length 74.9
  Top Layer w10: R39.2@1846.5,539 1869.84,539 D5.1@1906.27,502.57
NetD5_2: D5.2 R40.2 | length 60.2
  Top Layer w10: R40.2@1846.5,477 1847.5,476 D5.2@1906.27,476
NetD5_3: D5.3 R41.2 | length 74.4
  Top Layer w10: R41.2@1846.5,414 1870.84,414 D5.3@1906.27,449.43
NetJ4_1: J4.1 R22.2 U3.6 | length 538.8
  Top Layer w20: U3.6@1289,1603.28 1289,1646 1296.01,1653.01 R22.2@1296.01,1695 1296.01,1887.01 1364,1955 J4.1@1364,2111
NetJ4_3: J4.3 R21.2 U3.7 | length 538.8
  Top Layer w20: J4.3@1164,2111 1164,1942 1229,1877 R21.2@1229,1695 1229,1650 1239,1640 U3.7@1239,1603.28
NetJ5_1: J5.1 R30.1 RV1.2 U5.3 | length 565.4
  Bottom Layer w40: J5.1@656,2111 R30.1@756,2111 855,2111 953.64,2012.36 RV1.2@953.64,1928.6 890.4,1928.6 860.73,1898.92 U5.3@860.73,1861
NetJ5_3: J5.3 R31.2 RV2.1 U7.3 | length 532.1
  Bottom Layer w40: U7.3@148.28,1861 148.36,1861.09 RV2.1@148.36,2003.4 148.36,2067.36 192,2111 R31.2@356,2111 J5.3@456,2111
NetR1_1: R1.1 U1.56 | length 99.6
  Top Layer w10: 1435.16,486.34 U1.56@1435.16,529.61
  Top Layer w20: 1435.16,486.34 R1.1@1475,446.5
NetR4_1: R4.1 U1.54 | length 89
  Top Layer w10: 1395.79,485 U1.54@1395.79,529.61
  Top Layer w20: 1395.79,485 1395.79,460.71 R4.1@1410,446.5
NetR6_1: R6.1 U1.51 | length 119.7
  Top Layer w10: R6.1@1280.77,436.5 1285.31,436.5 1336.73,487.92 U1.51@1336.73,529.61
  Top Layer w15: R6.1@1280,436.5 R6.1@1280.77,436.5
NetR8_1: R8.1 U1.39 | length 111.6
  Top Layer w10: R8.1@1116.5,805 1136.97,784.53 U1.39@1219.61,784.53
NetR9_1: R9.1 U1.35 | length 116.3
  Top Layer w10: 1169.02,869.99 1175.73,863.27 U1.35@1219.61,863.27
  Top Layer w15: R9.1@1116.5,895 1144,895 1169.02,869.99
